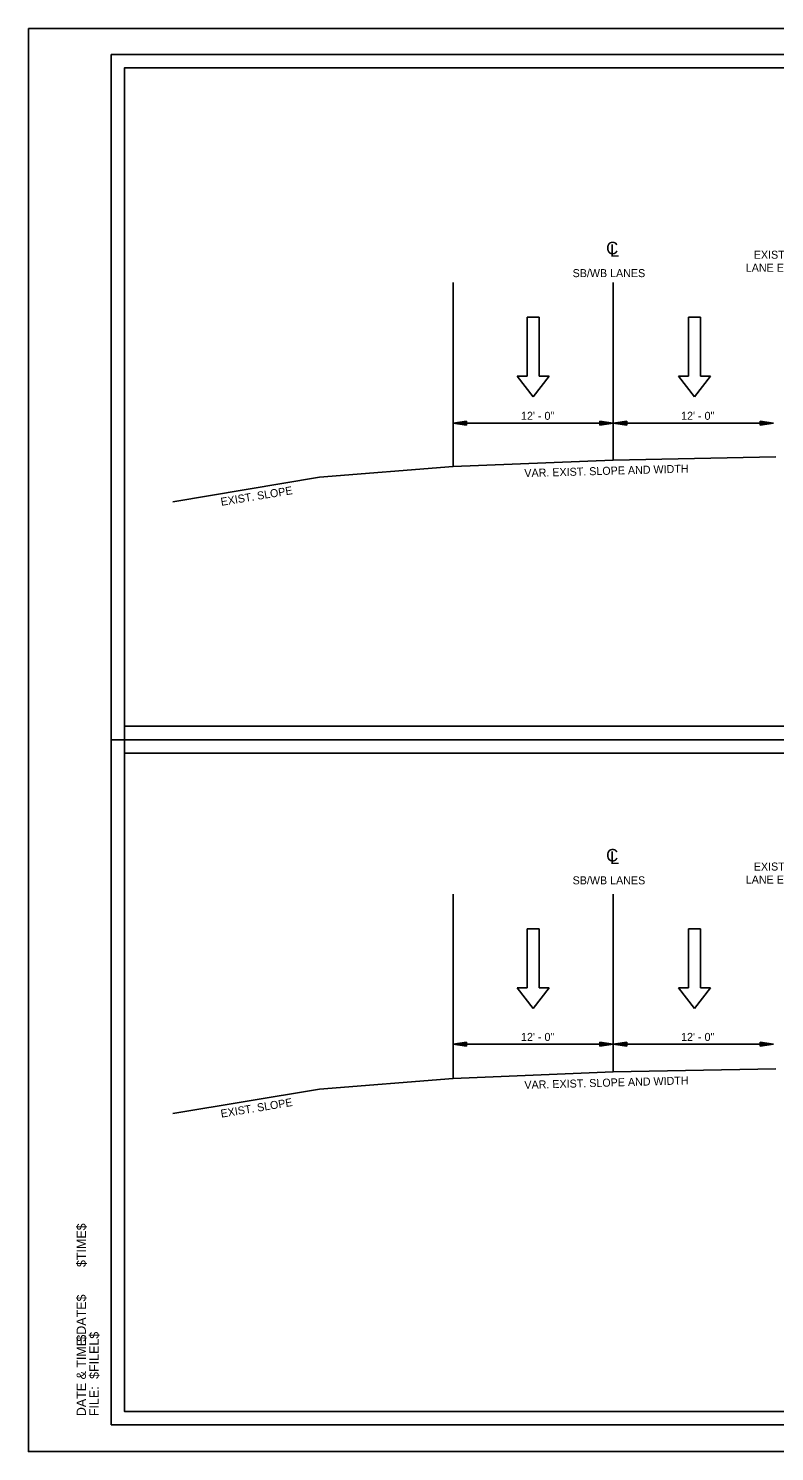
# Model space of a CAD drawing. Extents: x 1373889 to 1374222, y 382002 to 382215.
# Drawn here: x 1373888.5 to 1374000.3, y 382001.7 to 382215 of the extents above; entities that cross this region are included whole.
import ezdxf

# ---------------------------------------------------------------- set-up
doc = ezdxf.new("R2010")
doc.units = 0
for name, color, linetype in [('R_Border', 7, 'Continuous'), ('R_Border Notes', 7, 'Continuous'), ('R_Border Plan-Plan', 7, 'Continuous'), ('R_Draft', 7, 'Continuous'), ('R_No Plot', 7, 'Continuous'), ('R_Striping', 7, 'Continuous')]:
    doc.layers.add(name, color=color, linetype=linetype)

msp = doc.modelspace()

# ---------------------------------------------------------------- linework, layer by layer
at = {"layer": 'R_Border'}
for p, q in [((1373900.91, 382211.12), (1374217.09, 382211.12)), ((1373900.91, 382005.66), (1373900.91, 382211.12)), ((1373900.91, 382005.66), (1373900.91, 382005.66)), ((1374217.09, 382005.66), (1373900.91, 382005.66))]:
    msp.add_line(p, q, dxfattribs=at)
at = {"layer": 'R_Border Plan-Plan'}
msp.add_line((1373900.91, 382108.39), (1374217.09, 382108.39), dxfattribs=at)
at = {"layer": 'R_Draft'}
for p, q in [((1373952.14, 382149.34), (1373952.14, 382176.95)), ((1373976.12, 382150.3), (1373976.12, 382176.95)), ((1373954.14, 382156.14), (1373952.14, 382155.84)), ((1373954.14, 382156.09), (1373952.47, 382155.84)), ((1373954.14, 382156.03), (1373952.81, 382155.84)), ((1373954.14, 382155.98), (1373953.15, 382155.84)), ((1373954.14, 382155.93), (1373953.49, 382155.84)), ((1373954.14, 382155.54), (1373954.14, 382156.14)), ((1373974.12, 382156.14), (1373976.12, 382155.84)), ((1373974.12, 382155.54), (1373974.12, 382156.14)), ((1373974.12, 382156.09), (1373975.78, 382155.84)), ((1373974.12, 382156.03), (1373975.44, 382155.84)), ((1373974.12, 382155.98), (1373975.11, 382155.84)), ((1373974.12, 382155.93), (1373974.77, 382155.84)), ((1373978.12, 382156.14), (1373976.12, 382155.84)), ((1373978.12, 382156.09), (1373976.45, 382155.84)), ((1373978.12, 382156.03), (1373976.8, 382155.84)), ((1373978.12, 382155.98), (1373977.13, 382155.84)), ((1373978.12, 382155.93), (1373977.47, 382155.84)), ((1373978.12, 382155.54), (1373978.12, 382156.14)), ((1373998.1, 382156.14), (1374000.1, 382155.84)), ((1373998.1, 382155.54), (1373998.1, 382156.14)), ((1373998.1, 382156.09), (1373999.76, 382155.84)), ((1373998.1, 382156.03), (1373999.42, 382155.84)), ((1373998.1, 382155.98), (1373999.09, 382155.84)), ((1373998.1, 382155.93), (1373998.75, 382155.84)), ((1373952.14, 382155.84), (1373976.12, 382155.84)), ((1373954.14, 382155.54), (1373952.14, 382155.84)), ((1373954.14, 382155.59), (1373952.47, 382155.84)), ((1373954.14, 382155.64), (1373952.81, 382155.84)), ((1373954.14, 382155.69), (1373953.15, 382155.84)), ((1373954.14, 382155.74), (1373953.49, 382155.84)), ((1373954.14, 382155.88), (1373953.82, 382155.84)), ((1373954.14, 382155.79), (1373953.82, 382155.84)), ((1373974.12, 382155.88), (1373974.43, 382155.84)), ((1373974.12, 382155.54), (1373976.12, 382155.84)), ((1373974.12, 382155.74), (1373974.77, 382155.84)), ((1373974.12, 382155.64), (1373975.44, 382155.84)), ((1373974.12, 382155.59), (1373975.78, 382155.84)), ((1373974.12, 382155.69), (1373975.11, 382155.84)), ((1373974.12, 382155.79), (1373974.43, 382155.84)), ((1373976.12, 382155.84), (1374000.1, 382155.84)), ((1373978.12, 382155.54), (1373976.12, 382155.84)), ((1373978.12, 382155.59), (1373976.45, 382155.84)), ((1373978.12, 382155.64), (1373976.8, 382155.84)), ((1373978.12, 382155.69), (1373977.13, 382155.84)), ((1373978.12, 382155.74), (1373977.47, 382155.84)), ((1373978.12, 382155.88), (1373977.8, 382155.84)), ((1373978.12, 382155.79), (1373977.8, 382155.84)), ((1373998.1, 382155.88), (1373998.41, 382155.84)), ((1373998.1, 382155.54), (1374000.1, 382155.84)), ((1373998.1, 382155.74), (1373998.75, 382155.84)), ((1373998.1, 382155.64), (1373999.42, 382155.84)), ((1373998.1, 382155.59), (1373999.76, 382155.84)), ((1373998.1, 382155.69), (1373999.09, 382155.84)), ((1373998.1, 382155.79), (1373998.41, 382155.84)), ((1373976.11, 382150.3), (1373952.14, 382149.34)), ((1374000.44, 382150.78), (1373976.12, 382150.3)), ((1373932.11, 382147.73), (1373910.11, 382144.06)), ((1373952.14, 382149.34), (1373932.11, 382147.73)), ((1373952.14, 382057.62), (1373952.14, 382085.23)), ((1373976.12, 382058.58), (1373976.12, 382085.23)), ((1373954.14, 382063.03), (1373952.14, 382062.73)), ((1373952.14, 382062.73), (1373976.12, 382062.73)), ((1373954.14, 382062.43), (1373952.14, 382062.73)), ((1373954.14, 382062.98), (1373952.47, 382062.73)), ((1373954.14, 382062.48), (1373952.47, 382062.73)), ((1373954.14, 382062.93), (1373952.81, 382062.73)), ((1373954.14, 382062.53), (1373952.81, 382062.73)), ((1373954.14, 382062.88), (1373953.15, 382062.73)), ((1373954.14, 382062.58), (1373953.15, 382062.73)), ((1373954.14, 382062.83), (1373953.49, 382062.73)), ((1373954.14, 382062.63), (1373953.49, 382062.73)), ((1373954.14, 382062.77), (1373953.82, 382062.73)), ((1373954.14, 382062.68), (1373953.82, 382062.73)), ((1373954.14, 382062.43), (1373954.14, 382063.03)), ((1373974.12, 382063.03), (1373976.12, 382062.73)), ((1373974.12, 382062.43), (1373974.12, 382063.03)), ((1373974.12, 382062.98), (1373975.78, 382062.73)), ((1373974.12, 382062.93), (1373975.44, 382062.73)), ((1373974.12, 382062.88), (1373975.11, 382062.73)), ((1373974.12, 382062.83), (1373974.77, 382062.73)), ((1373974.12, 382062.77), (1373974.43, 382062.73)), ((1373974.12, 382062.43), (1373976.12, 382062.73)), ((1373974.12, 382062.63), (1373974.77, 382062.73)), ((1373974.12, 382062.53), (1373975.44, 382062.73)), ((1373974.12, 382062.48), (1373975.78, 382062.73)), ((1373974.12, 382062.58), (1373975.11, 382062.73)), ((1373974.12, 382062.68), (1373974.43, 382062.73)), ((1373978.12, 382063.03), (1373976.12, 382062.73)), ((1373976.12, 382062.73), (1374000.1, 382062.73)), ((1373978.12, 382062.43), (1373976.12, 382062.73)), ((1373978.12, 382062.98), (1373976.45, 382062.73)), ((1373978.12, 382062.48), (1373976.45, 382062.73)), ((1373978.12, 382062.93), (1373976.8, 382062.73)), ((1373978.12, 382062.53), (1373976.8, 382062.73)), ((1373978.12, 382062.88), (1373977.13, 382062.73)), ((1373978.12, 382062.58), (1373977.13, 382062.73)), ((1373978.12, 382062.83), (1373977.47, 382062.73)), ((1373978.12, 382062.63), (1373977.47, 382062.73)), ((1373978.12, 382062.77), (1373977.8, 382062.73)), ((1373978.12, 382062.68), (1373977.8, 382062.73)), ((1373978.12, 382062.43), (1373978.12, 382063.03)), ((1373998.1, 382063.03), (1374000.1, 382062.73)), ((1373998.1, 382062.43), (1373998.1, 382063.03)), ((1373998.1, 382062.98), (1373999.76, 382062.73)), ((1373998.1, 382062.93), (1373999.42, 382062.73)), ((1373998.1, 382062.88), (1373999.09, 382062.73)), ((1373998.1, 382062.83), (1373998.75, 382062.73)), ((1373998.1, 382062.77), (1373998.41, 382062.73)), ((1373998.1, 382062.43), (1374000.1, 382062.73)), ((1373998.1, 382062.63), (1373998.75, 382062.73)), ((1373998.1, 382062.53), (1373999.42, 382062.73)), ((1373998.1, 382062.48), (1373999.76, 382062.73)), ((1373998.1, 382062.58), (1373999.09, 382062.73)), ((1373998.1, 382062.68), (1373998.41, 382062.73)), ((1373976.11, 382058.58), (1373952.14, 382057.62)), ((1374000.44, 382059.06), (1373976.12, 382058.58)), ((1373932.11, 382056.01), (1373910.11, 382052.34)), ((1373952.14, 382057.62), (1373932.11, 382056.01))]:
    msp.add_line(p, q, dxfattribs=at)
at = {"layer": 'R_No Plot'}
for points in [[(1373888.51, 382215.01), (1374221.85, 382215.01), (1374221.85, 382001.67), (1373888.51, 382001.67)], [(1374215.09, 382110.39), (1373902.91, 382110.39), (1373902.91, 382209.12), (1374152.45, 382209.12), (1374152.45, 382199.24), (1374169.99, 382199.24), (1374194.09, 382199.24), (1374194.09, 382176.9), (1374215.09, 382176.9)], [(1373902.91, 382209.12), (1374152.45, 382209.12), (1374152.45, 382199.24), (1374169.99, 382199.24), (1374194.09, 382199.24), (1374194.09, 382176.9), (1374215.09, 382176.9), (1374215.09, 382007.66), (1373902.91, 382007.66)], [(1373902.91, 382106.39), (1374215.09, 382106.39), (1374215.09, 382007.66), (1373902.91, 382007.66)]]:
    msp.add_lwpolyline(points, close=True, dxfattribs=at)
at = {"layer": 'R_Striping'}
for p, q in [((1373963.22, 382162.9), (1373963.22, 382171.73)), ((1373965.02, 382171.73), (1373963.22, 382171.73)), ((1373965.02, 382162.9), (1373965.02, 382171.73)), ((1373987.38, 382162.9), (1373987.38, 382171.73)), ((1373989.18, 382171.73), (1373987.38, 382171.73)), ((1373989.18, 382162.9), (1373989.18, 382171.73)), ((1373963.22, 382162.9), (1373961.72, 382162.9)), ((1373964.12, 382159.79), (1373961.72, 382162.9)), ((1373966.52, 382162.9), (1373964.12, 382159.79)), ((1373966.52, 382162.9), (1373965.02, 382162.9)), ((1373987.38, 382162.9), (1373985.88, 382162.9)), ((1373988.28, 382159.79), (1373985.88, 382162.9)), ((1373990.68, 382162.9), (1373988.28, 382159.79)), ((1373990.68, 382162.9), (1373989.18, 382162.9)), ((1373963.22, 382071.18), (1373963.22, 382080.01)), ((1373965.02, 382080.01), (1373963.22, 382080.01)), ((1373965.02, 382071.18), (1373965.02, 382080.01)), ((1373987.38, 382071.18), (1373987.38, 382080.01)), ((1373989.18, 382080.01), (1373987.38, 382080.01)), ((1373989.18, 382071.18), (1373989.18, 382080.01)), ((1373963.22, 382071.18), (1373961.72, 382071.18)), ((1373964.12, 382068.07), (1373961.72, 382071.18)), ((1373966.52, 382071.18), (1373964.12, 382068.07)), ((1373966.52, 382071.18), (1373965.02, 382071.18)), ((1373987.38, 382071.18), (1373985.88, 382071.18)), ((1373988.28, 382068.07), (1373985.88, 382071.18)), ((1373990.68, 382071.18), (1373988.28, 382068.07)), ((1373990.68, 382071.18), (1373989.18, 382071.18))]:
    msp.add_line(p, q, dxfattribs=at)

# ---------------------------------------------------------------- texts
at = {"layer": 'R_Border Notes'}
for s, height, p in [('$TIME$', 1.397, (1373897.11, 382029.33)), ('$DATE$', 1.397, (1373897.11, 382018.15)), ('$FILEL$', 1.397, (1373899.04, 382012.56)), ('DATE & TIME:', 1.3968, (1373897.11, 382006.98)), ('FILE: ', 1.397, (1373899.04, 382006.98))]:
    msp.add_text(s, height=height, rotation=90, dxfattribs=at).set_placement(p)
at = {"layer": 'R_Draft'}
for s, height, p in [('C', 1.88, (1373975.04, 382181.15)), ('L', 1.88, (1373975.61, 382180.79)), ('EXISTING', 1.2, (1373997.16, 382180.49)), ('LANE EDGE', 1.2, (1373995.96, 382178.54)), ('SB/WB LANES', 1.2, (1373970.02, 382177.73)), ('12\' - 0"', 1.2, (1373962.29, 382156.34)), ('12\' - 0"', 1.2, (1373986.27, 382156.34)), ('C', 1.88, (1373975.04, 382090.13)), ('L', 1.88, (1373975.61, 382089.76)), ('EXISTING', 1.2, (1373997.16, 382088.77)), ('SB/WB LANES', 1.2, (1373970.02, 382086.7)), ('LANE EDGE', 1.2, (1373995.96, 382086.82)), ('12\' - 0"', 1.2, (1373962.29, 382063.23)), ('12\' - 0"', 1.2, (1373986.27, 382063.23))]:
    msp.add_text(s, height=height, dxfattribs=at).set_placement(p)
for s, rotation, p in [('VAR. EXIST. SLOPE AND WIDTH', 1.6054, (1373962.81, 382147.75)), ('EXIST. SLOPE', 9.361, (1373917.4, 382143.44)), ('VAR. EXIST. SLOPE AND WIDTH', 1.6054, (1373962.81, 382056.03)), ('EXIST. SLOPE', 9.361, (1373917.4, 382051.72))]:
    msp.add_text(s, height=1.2, rotation=rotation, dxfattribs=at).set_placement(p)

doc.saveas('drawing.dxf')
